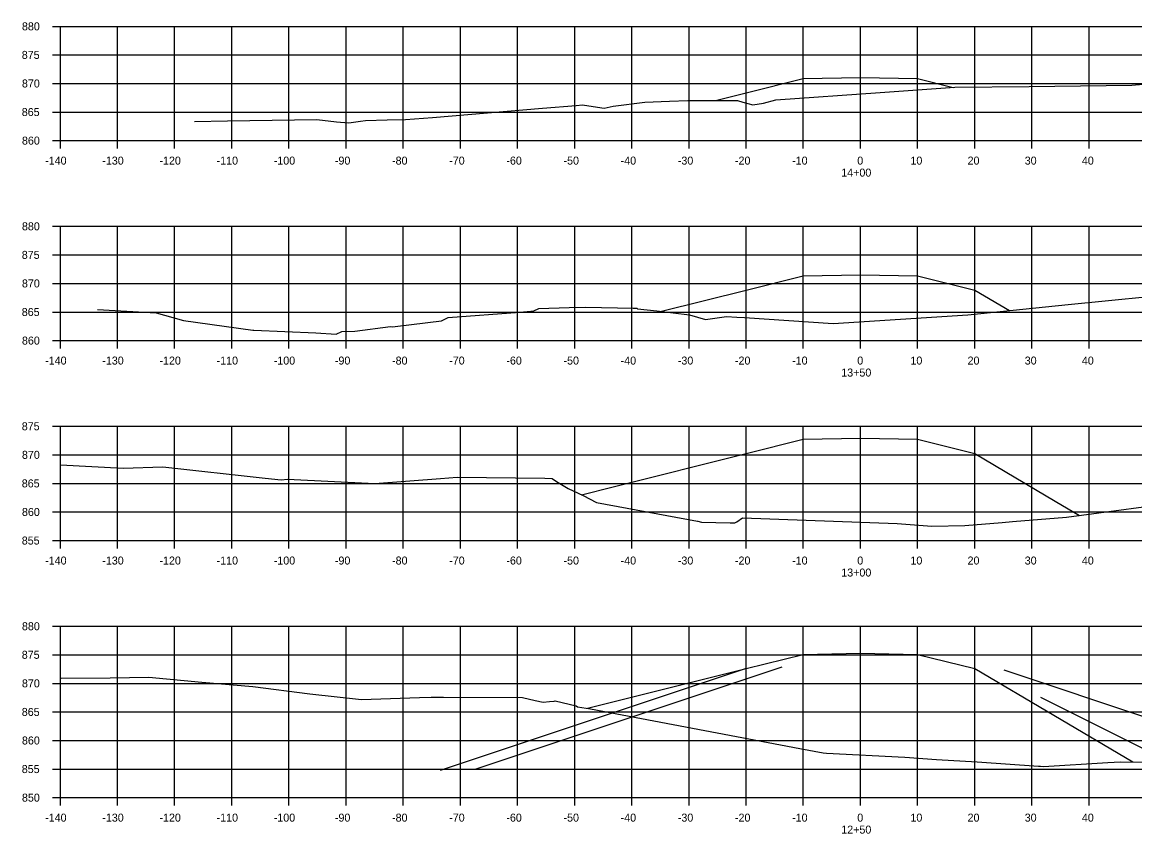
# Model space of a CAD drawing. Extents: x 1098669 to 1198896, y 698679 to 704410.
# Drawn here: x 1110634.5 to 1110829.2, y 701792.8 to 701934.8 of the extents above; entities that cross this region are included whole.
import ezdxf

# ---------------------------------------------------------------- set-up
doc = ezdxf.new("R2010")
doc.units = 0
for name, color, linetype in [('Proposed Surface', 7, 'Continuous'), ('R_Axis', 7, 'Continuous'), ('R_Axis Annot', 7, 'Continuous'), ('R_Fin Surface', 7, 'Continuous'), ('R_Grid', 7, 'Continuous'), ('R_Water', 7, 'Continuous')]:
    doc.layers.add(name, color=color, linetype=linetype)

msp = doc.modelspace()

# ---------------------------------------------------------------- linework, layer by layer
at = {"layer": 'Proposed Surface'}
for points in [[(1110664.64, 701917.49), (1110670.39, 701917.57), (1110686.06, 701917.85), (1110689.48, 701917.41), (1110691.65, 701917.24), (1110693.67, 701917.53), (1110694.56, 701917.63), (1110698.32, 701917.76), (1110701.55, 701917.84), (1110706.25, 701918.18), (1110725.54, 701919.81), (1110731.4, 701920.3), (1110732.51, 701920.4), (1110732.86, 701920.33), (1110736.3, 701919.81), (1110737.87, 701920.15), (1110743.45, 701920.87), (1110747.75, 701921.02), (1110750.94, 701921.16), (1110756.38, 701921.15), (1110759.62, 701921.16), (1110760.56, 701920.83), (1110762.31, 701920.41), (1110764.2, 701920.71), (1110766.33, 701921.26), (1110784.63, 701922.56), (1110797.65, 701923.47), (1110810.65, 701923.59), (1110828.64, 701923.84), (1110855.84, 701926.22)], [(1110647.65, 701884.57), (1110657.9, 701883.97), (1110662.69, 701882.64), (1110674.82, 701880.94), (1110674.9, 701880.94), (1110674.99, 701880.93), (1110685.87, 701880.49), (1110689.44, 701880.25), (1110690.42, 701880.69), (1110692.66, 701880.78), (1110698.92, 701881.57), (1110699.2, 701881.54), (1110699.74, 701881.61), (1110707.83, 701882.61), (1110709.02, 701883.16), (1110721.53, 701884.1), (1110723.47, 701884.26), (1110723.98, 701884.32), (1110724.87, 701884.77), (1110730.21, 701884.9), (1110733.09, 701884.99), (1110741.41, 701884.81), (1110742.1, 701884.8), (1110742.15, 701884.71), (1110745.52, 701884.35), (1110751.27, 701883.62), (1110754.03, 701882.84), (1110757.7, 701883.35), (1110759.53, 701883.25), (1110760.88, 701883.17), (1110776.39, 701882.14), (1110799.97, 701883.63), (1110817.53, 701885.44), (1110838.66, 701887.55)], [(1110641.16, 701857.38), (1110652.17, 701856.81), (1110659.12, 701857.04), (1110676.98, 701855.07), (1110679.8, 701854.78), (1110680.89, 701854.86), (1110696.21, 701854.12), (1110707.68, 701854.97), (1110710.59, 701855.23), (1110725.92, 701855.02), (1110727.19, 701855.01), (1110727.97, 701854.46), (1110730.04, 701853.25), (1110732.63, 701852), (1110734.96, 701850.81), (1110752.64, 701847.54), (1110752.69, 701847.53), (1110752.7, 701847.53), (1110752.7, 701847.53), (1110753.36, 701847.32), (1110758.38, 701847.25), (1110759.16, 701847.23), (1110759.54, 701847.41), (1110760.5, 701848.09), (1110787.57, 701847.1), (1110793.64, 701846.65), (1110799.45, 701846.78), (1110805.96, 701847.31), (1110807.76, 701847.46), (1110817.23, 701848.23), (1110838.97, 701851.16)], [(1110641.16, 701820.03), (1110641.31, 701820.04), (1110649.9, 701820.07), (1110656.67, 701820.23), (1110665.91, 701819.35), (1110674.86, 701818.58), (1110684.81, 701817.31), (1110693.87, 701816.29), (1110704.03, 701816.65), (1110706.07, 701816.73), (1110708.23, 701816.74), (1110722.04, 701816.66), (1110724.26, 701816.12), (1110725.66, 701815.82), (1110726.72, 701815.93), (1110727.58, 701816.04), (1110727.75, 701816.06), (1110731.42, 701815.17), (1110731.64, 701815.04), (1110733.9, 701814.69), (1110770.56, 701807.73), (1110774.65, 701806.96), (1110775.2, 701806.92), (1110788.9, 701806.19), (1110794.44, 701805.82), (1110801.58, 701805.42), (1110812.3, 701804.65), (1110812.64, 701804.63), (1110813.18, 701804.59), (1110824.42, 701805.27), (1110826.68, 701805.42), (1110835.43, 701805.36)]]:
    msp.add_lwpolyline(points, dxfattribs=at)
at = {"layer": 'R_Axis'}
for p, q in [((1110639.76, 701934.13), (1110641.16, 701934.13)), ((1110641.16, 701914.13), (1110641.16, 701934.13)), ((1110639.76, 701929.13), (1110641.16, 701929.13)), ((1110639.76, 701924.13), (1110641.16, 701924.13)), ((1110639.76, 701919.13), (1110641.16, 701919.13)), ((1110639.76, 701914.13), (1110641.16, 701914.13)), ((1110641.16, 701914.13), (1110921.16, 701914.13)), ((1110641.16, 701912.73), (1110641.16, 701914.13)), ((1110651.16, 701912.73), (1110651.16, 701914.13)), ((1110661.16, 701912.73), (1110661.16, 701914.13)), ((1110671.16, 701912.73), (1110671.16, 701914.13)), ((1110681.16, 701912.73), (1110681.16, 701914.13)), ((1110691.16, 701912.73), (1110691.16, 701914.13)), ((1110701.16, 701912.73), (1110701.16, 701914.13)), ((1110711.16, 701912.73), (1110711.16, 701914.13)), ((1110721.16, 701912.73), (1110721.16, 701914.13)), ((1110731.16, 701912.73), (1110731.16, 701914.13)), ((1110741.16, 701912.73), (1110741.16, 701914.13)), ((1110751.16, 701912.73), (1110751.16, 701914.13)), ((1110761.16, 701912.73), (1110761.16, 701914.13)), ((1110771.16, 701912.73), (1110771.16, 701914.13)), ((1110781.16, 701912.73), (1110781.16, 701914.13)), ((1110791.16, 701912.73), (1110791.16, 701914.13)), ((1110801.16, 701912.73), (1110801.16, 701914.13)), ((1110811.16, 701912.73), (1110811.16, 701914.13)), ((1110821.16, 701912.73), (1110821.16, 701914.13)), ((1110639.76, 701899.13), (1110641.16, 701899.13)), ((1110641.16, 701879.13), (1110641.16, 701899.13)), ((1110639.76, 701894.13), (1110641.16, 701894.13)), ((1110639.76, 701889.13), (1110641.16, 701889.13)), ((1110639.76, 701884.13), (1110641.16, 701884.13)), ((1110639.76, 701879.13), (1110641.16, 701879.13)), ((1110641.16, 701879.13), (1110921.16, 701879.13)), ((1110641.16, 701877.73), (1110641.16, 701879.13)), ((1110651.16, 701877.73), (1110651.16, 701879.13)), ((1110661.16, 701877.73), (1110661.16, 701879.13)), ((1110671.16, 701877.73), (1110671.16, 701879.13)), ((1110681.16, 701877.73), (1110681.16, 701879.13)), ((1110691.16, 701877.73), (1110691.16, 701879.13)), ((1110701.16, 701877.73), (1110701.16, 701879.13)), ((1110711.16, 701877.73), (1110711.16, 701879.13)), ((1110721.16, 701877.73), (1110721.16, 701879.13)), ((1110731.16, 701877.73), (1110731.16, 701879.13)), ((1110741.16, 701877.73), (1110741.16, 701879.13)), ((1110751.16, 701877.73), (1110751.16, 701879.13)), ((1110761.16, 701877.73), (1110761.16, 701879.13)), ((1110771.16, 701877.73), (1110771.16, 701879.13)), ((1110781.16, 701877.73), (1110781.16, 701879.13)), ((1110791.16, 701877.73), (1110791.16, 701879.13)), ((1110801.16, 701877.73), (1110801.16, 701879.13)), ((1110811.16, 701877.73), (1110811.16, 701879.13)), ((1110821.16, 701877.73), (1110821.16, 701879.13)), ((1110639.76, 701864.13), (1110641.16, 701864.13)), ((1110641.16, 701844.13), (1110641.16, 701864.13)), ((1110639.76, 701859.13), (1110641.16, 701859.13)), ((1110639.76, 701854.13), (1110641.16, 701854.13)), ((1110639.76, 701849.13), (1110641.16, 701849.13)), ((1110639.76, 701844.13), (1110641.16, 701844.13)), ((1110641.16, 701844.13), (1110921.16, 701844.13)), ((1110641.16, 701842.73), (1110641.16, 701844.13)), ((1110651.16, 701842.73), (1110651.16, 701844.13)), ((1110661.16, 701842.73), (1110661.16, 701844.13)), ((1110671.16, 701842.73), (1110671.16, 701844.13)), ((1110681.16, 701842.73), (1110681.16, 701844.13)), ((1110691.16, 701842.73), (1110691.16, 701844.13)), ((1110701.16, 701842.73), (1110701.16, 701844.13)), ((1110711.16, 701842.73), (1110711.16, 701844.13)), ((1110721.16, 701842.73), (1110721.16, 701844.13)), ((1110731.16, 701842.73), (1110731.16, 701844.13)), ((1110741.16, 701842.73), (1110741.16, 701844.13)), ((1110751.16, 701842.73), (1110751.16, 701844.13)), ((1110761.16, 701842.73), (1110761.16, 701844.13)), ((1110771.16, 701842.73), (1110771.16, 701844.13)), ((1110781.16, 701842.73), (1110781.16, 701844.13)), ((1110791.16, 701842.73), (1110791.16, 701844.13)), ((1110801.16, 701842.73), (1110801.16, 701844.13)), ((1110811.16, 701842.73), (1110811.16, 701844.13)), ((1110821.16, 701842.73), (1110821.16, 701844.13)), ((1110639.76, 701829.13), (1110641.16, 701829.13)), ((1110641.16, 701799.13), (1110641.16, 701829.13)), ((1110639.76, 701824.13), (1110641.16, 701824.13)), ((1110639.76, 701819.13), (1110641.16, 701819.13)), ((1110639.76, 701814.13), (1110641.16, 701814.13)), ((1110639.76, 701809.13), (1110641.16, 701809.13)), ((1110639.76, 701804.13), (1110641.16, 701804.13)), ((1110639.76, 701799.13), (1110641.16, 701799.13)), ((1110641.16, 701799.13), (1110921.16, 701799.13)), ((1110641.16, 701797.73), (1110641.16, 701799.13)), ((1110651.16, 701797.73), (1110651.16, 701799.13)), ((1110661.16, 701797.73), (1110661.16, 701799.13)), ((1110671.16, 701797.73), (1110671.16, 701799.13)), ((1110681.16, 701797.73), (1110681.16, 701799.13)), ((1110691.16, 701797.73), (1110691.16, 701799.13)), ((1110701.16, 701797.73), (1110701.16, 701799.13)), ((1110711.16, 701797.73), (1110711.16, 701799.13)), ((1110721.16, 701797.73), (1110721.16, 701799.13)), ((1110731.16, 701797.73), (1110731.16, 701799.13)), ((1110741.16, 701797.73), (1110741.16, 701799.13)), ((1110751.16, 701797.73), (1110751.16, 701799.13)), ((1110761.16, 701797.73), (1110761.16, 701799.13)), ((1110771.16, 701797.73), (1110771.16, 701799.13)), ((1110781.16, 701797.73), (1110781.16, 701799.13)), ((1110791.16, 701797.73), (1110791.16, 701799.13)), ((1110801.16, 701797.73), (1110801.16, 701799.13)), ((1110811.16, 701797.73), (1110811.16, 701799.13)), ((1110821.16, 701797.73), (1110821.16, 701799.13))]:
    msp.add_line(p, q, dxfattribs=at)
at = {"layer": 'R_Fin Surface'}
for points in [[(1110755.77, 701921.15), (1110761.16, 701922.5), (1110771.16, 701925), (1110781.16, 701925.2), (1110791.16, 701925), (1110797.36, 701923.45)], [(1110746.33, 701884.25), (1110761.16, 701887.95), (1110771.16, 701890.45), (1110781.16, 701890.65), (1110791.16, 701890.45), (1110801.16, 701887.95), (1110807.23, 701884.38)], [(1110732.32, 701852.15), (1110737.88, 701853.54), (1110761.16, 701859.36), (1110771.16, 701861.86), (1110781.16, 701862.06), (1110791.16, 701861.86), (1110801.16, 701859.36), (1110815.25, 701851.05), (1110819.51, 701848.54)], [(1110733.4, 701814.77), (1110761.16, 701821.71), (1110771.16, 701824.21), (1110781.16, 701824.41), (1110791.16, 701824.21), (1110801.16, 701821.71), (1110828.8, 701805.41)]]:
    msp.add_lwpolyline(points, dxfattribs=at)
at = {"layer": 'R_Grid'}
for p, q in [((1110641.16, 701934.13), (1110921.16, 701934.13)), ((1110641.16, 701914.13), (1110641.16, 701934.13)), ((1110651.16, 701914.13), (1110651.16, 701934.13)), ((1110661.16, 701914.13), (1110661.16, 701934.13)), ((1110671.16, 701914.13), (1110671.16, 701934.13)), ((1110681.16, 701914.13), (1110681.16, 701934.13)), ((1110691.16, 701914.13), (1110691.16, 701934.13)), ((1110701.16, 701914.13), (1110701.16, 701934.13)), ((1110711.16, 701914.13), (1110711.16, 701934.13)), ((1110721.16, 701914.13), (1110721.16, 701934.13)), ((1110731.16, 701914.13), (1110731.16, 701934.13)), ((1110741.16, 701914.13), (1110741.16, 701934.13)), ((1110751.16, 701914.13), (1110751.16, 701934.13)), ((1110761.16, 701914.13), (1110761.16, 701934.13)), ((1110771.16, 701914.13), (1110771.16, 701934.13)), ((1110781.16, 701914.13), (1110781.16, 701934.13)), ((1110791.16, 701914.13), (1110791.16, 701934.13)), ((1110801.16, 701914.13), (1110801.16, 701934.13)), ((1110811.16, 701914.13), (1110811.16, 701934.13)), ((1110821.16, 701914.13), (1110821.16, 701934.13)), ((1110641.16, 701929.13), (1110921.16, 701929.13)), ((1110641.16, 701924.13), (1110921.16, 701924.13)), ((1110641.16, 701919.13), (1110921.16, 701919.13)), ((1110641.16, 701914.13), (1110921.16, 701914.13)), ((1110641.16, 701899.13), (1110921.16, 701899.13)), ((1110641.16, 701879.13), (1110641.16, 701899.13)), ((1110651.16, 701879.13), (1110651.16, 701899.13)), ((1110661.16, 701879.13), (1110661.16, 701899.13)), ((1110671.16, 701879.13), (1110671.16, 701899.13)), ((1110681.16, 701879.13), (1110681.16, 701899.13)), ((1110691.16, 701879.13), (1110691.16, 701899.13)), ((1110701.16, 701879.13), (1110701.16, 701899.13)), ((1110711.16, 701879.13), (1110711.16, 701899.13)), ((1110721.16, 701879.13), (1110721.16, 701899.13)), ((1110731.16, 701879.13), (1110731.16, 701899.13)), ((1110741.16, 701879.13), (1110741.16, 701899.13)), ((1110751.16, 701879.13), (1110751.16, 701899.13)), ((1110761.16, 701879.13), (1110761.16, 701899.13)), ((1110771.16, 701879.13), (1110771.16, 701899.13)), ((1110781.16, 701879.13), (1110781.16, 701899.13)), ((1110791.16, 701879.13), (1110791.16, 701899.13)), ((1110801.16, 701879.13), (1110801.16, 701899.13)), ((1110811.16, 701879.13), (1110811.16, 701899.13)), ((1110821.16, 701879.13), (1110821.16, 701899.13)), ((1110641.16, 701894.13), (1110921.16, 701894.13)), ((1110641.16, 701889.13), (1110921.16, 701889.13)), ((1110641.16, 701884.13), (1110921.16, 701884.13)), ((1110641.16, 701879.13), (1110921.16, 701879.13)), ((1110641.16, 701864.13), (1110921.16, 701864.13)), ((1110641.16, 701844.13), (1110641.16, 701864.13)), ((1110651.16, 701844.13), (1110651.16, 701864.13)), ((1110661.16, 701844.13), (1110661.16, 701864.13)), ((1110671.16, 701844.13), (1110671.16, 701864.13)), ((1110681.16, 701844.13), (1110681.16, 701864.13)), ((1110691.16, 701844.13), (1110691.16, 701864.13)), ((1110701.16, 701844.13), (1110701.16, 701864.13)), ((1110711.16, 701844.13), (1110711.16, 701864.13)), ((1110721.16, 701844.13), (1110721.16, 701864.13)), ((1110731.16, 701844.13), (1110731.16, 701864.13)), ((1110741.16, 701844.13), (1110741.16, 701864.13)), ((1110751.16, 701844.13), (1110751.16, 701864.13)), ((1110761.16, 701844.13), (1110761.16, 701864.13)), ((1110771.16, 701844.13), (1110771.16, 701864.13)), ((1110781.16, 701844.13), (1110781.16, 701864.13)), ((1110791.16, 701844.13), (1110791.16, 701864.13)), ((1110801.16, 701844.13), (1110801.16, 701864.13)), ((1110811.16, 701844.13), (1110811.16, 701864.13)), ((1110821.16, 701844.13), (1110821.16, 701864.13)), ((1110641.16, 701859.13), (1110921.16, 701859.13)), ((1110641.16, 701854.13), (1110921.16, 701854.13)), ((1110641.16, 701849.13), (1110921.16, 701849.13)), ((1110641.16, 701844.13), (1110921.16, 701844.13)), ((1110641.16, 701829.13), (1110921.16, 701829.13)), ((1110641.16, 701799.13), (1110641.16, 701829.13)), ((1110651.16, 701799.13), (1110651.16, 701829.13)), ((1110661.16, 701799.13), (1110661.16, 701829.13)), ((1110671.16, 701799.13), (1110671.16, 701829.13)), ((1110681.16, 701799.13), (1110681.16, 701829.13)), ((1110691.16, 701799.13), (1110691.16, 701829.13)), ((1110701.16, 701799.13), (1110701.16, 701829.13)), ((1110711.16, 701799.13), (1110711.16, 701829.13)), ((1110721.16, 701799.13), (1110721.16, 701829.13)), ((1110731.16, 701799.13), (1110731.16, 701829.13)), ((1110741.16, 701799.13), (1110741.16, 701829.13)), ((1110751.16, 701799.13), (1110751.16, 701829.13)), ((1110761.16, 701799.13), (1110761.16, 701829.13)), ((1110771.16, 701799.13), (1110771.16, 701829.13)), ((1110781.16, 701799.13), (1110781.16, 701829.13)), ((1110791.16, 701799.13), (1110791.16, 701829.13)), ((1110801.16, 701799.13), (1110801.16, 701829.13)), ((1110811.16, 701799.13), (1110811.16, 701829.13)), ((1110821.16, 701799.13), (1110821.16, 701829.13)), ((1110641.16, 701824.13), (1110921.16, 701824.13)), ((1110641.16, 701819.13), (1110921.16, 701819.13)), ((1110641.16, 701814.13), (1110921.16, 701814.13)), ((1110641.16, 701809.13), (1110921.16, 701809.13)), ((1110641.16, 701804.13), (1110921.16, 701804.13)), ((1110641.16, 701799.13), (1110921.16, 701799.13))]:
    msp.add_line(p, q, dxfattribs=at)
at = {"layer": 'R_Water'}
for points in [[(1110767.41, 701821.97), (1110713.87, 701804.13)], [(1110761.16, 701821.71), (1110707.62, 701803.86)], [(1110806.23, 701821.47), (1110858.25, 701804.13)], [(1110812.66, 701816.72), (1110835.39, 701805.36)]]:
    msp.add_lwpolyline(points, dxfattribs=at)

# ---------------------------------------------------------------- texts
at = {"layer": 'R_Axis Annot'}
for s, p in [('880', (1110634.44, 701933.43)), ('875', (1110634.41, 701928.43)), ('870', (1110634.44, 701923.43)), ('865', (1110634.41, 701918.43)), ('860', (1110634.44, 701913.43)), ('-140', (1110638.5, 701909.93)), ('-130', (1110648.5, 701909.93)), ('-120', (1110658.5, 701909.93)), ('-110', (1110668.5, 701909.93)), ('-100', (1110678.5, 701909.93)), ('-90', (1110689.2, 701909.93)), ('-80', (1110699.2, 701909.93)), ('-70', (1110709.2, 701909.93)), ('-60', (1110719.2, 701909.93)), ('-50', (1110729.2, 701909.93)), ('-40', (1110739.2, 701909.93)), ('-30', (1110749.2, 701909.93)), ('-20', (1110759.2, 701909.93)), ('-10', (1110769.2, 701909.93)), ('0', (1110780.6, 701909.93)), ('10', (1110789.9, 701909.93)), ('20', (1110799.9, 701909.93)), ('30', (1110809.9, 701909.93)), ('40', (1110819.9, 701909.93)), ('14+00', (1110777.8, 701907.83)), ('880', (1110634.44, 701898.43)), ('875', (1110634.41, 701893.43)), ('870', (1110634.44, 701888.43)), ('865', (1110634.41, 701883.43)), ('860', (1110634.44, 701878.43)), ('-140', (1110638.5, 701874.93)), ('-130', (1110648.5, 701874.93)), ('-120', (1110658.5, 701874.93)), ('-110', (1110668.5, 701874.93)), ('-100', (1110678.5, 701874.93)), ('-90', (1110689.2, 701874.93)), ('-80', (1110699.2, 701874.93)), ('-70', (1110709.2, 701874.93)), ('-60', (1110719.2, 701874.93)), ('-50', (1110729.2, 701874.93)), ('-40', (1110739.2, 701874.93)), ('-30', (1110749.2, 701874.93)), ('-20', (1110759.2, 701874.93)), ('-10', (1110769.2, 701874.93)), ('0', (1110780.6, 701874.93)), ('10', (1110789.9, 701874.93)), ('20', (1110799.9, 701874.93)), ('30', (1110809.9, 701874.93)), ('40', (1110819.9, 701874.93)), ('13+50', (1110777.8, 701872.83)), ('875', (1110634.41, 701863.43)), ('870', (1110634.44, 701858.43)), ('865', (1110634.41, 701853.43)), ('860', (1110634.44, 701848.43)), ('855', (1110634.41, 701843.43)), ('-140', (1110638.5, 701839.93)), ('-130', (1110648.5, 701839.93)), ('-120', (1110658.5, 701839.93)), ('-110', (1110668.5, 701839.93)), ('-100', (1110678.5, 701839.93)), ('-90', (1110689.2, 701839.93)), ('-80', (1110699.2, 701839.93)), ('-70', (1110709.2, 701839.93)), ('-60', (1110719.2, 701839.93)), ('-50', (1110729.2, 701839.93)), ('-40', (1110739.2, 701839.93)), ('-30', (1110749.2, 701839.93)), ('-20', (1110759.2, 701839.93)), ('-10', (1110769.2, 701839.93)), ('0', (1110780.6, 701839.93)), ('10', (1110789.9, 701839.93)), ('20', (1110799.9, 701839.93)), ('30', (1110809.9, 701839.93)), ('40', (1110819.9, 701839.93)), ('13+00', (1110777.8, 701837.83)), ('880', (1110634.44, 701828.43)), ('875', (1110634.41, 701823.43)), ('870', (1110634.44, 701818.43)), ('865', (1110634.41, 701813.43)), ('860', (1110634.44, 701808.43)), ('855', (1110634.41, 701803.43)), ('850', (1110634.44, 701798.43)), ('-140', (1110638.5, 701794.93)), ('-130', (1110648.5, 701794.93)), ('-120', (1110658.5, 701794.93)), ('-110', (1110668.5, 701794.93)), ('-100', (1110678.5, 701794.93)), ('-90', (1110689.2, 701794.93)), ('-80', (1110699.2, 701794.93)), ('-70', (1110709.2, 701794.93)), ('-60', (1110719.2, 701794.93)), ('-50', (1110729.2, 701794.93)), ('-40', (1110739.2, 701794.93)), ('-30', (1110749.2, 701794.93)), ('-20', (1110759.2, 701794.93)), ('-10', (1110769.2, 701794.93)), ('0', (1110780.6, 701794.93)), ('10', (1110789.9, 701794.93)), ('20', (1110799.9, 701794.93)), ('30', (1110809.9, 701794.93)), ('40', (1110819.9, 701794.93)), ('12+50', (1110777.8, 701792.83))]:
    msp.add_text(s, height=1.4, dxfattribs=at).set_placement(p)

doc.saveas('drawing.dxf')
